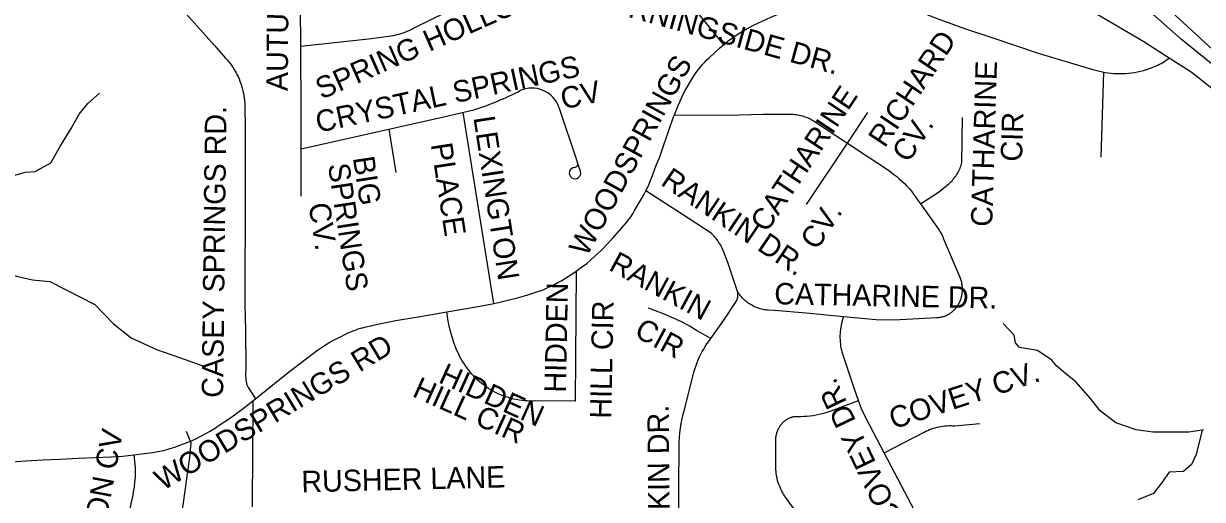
# Model space of a CAD drawing. Extents: x 1670563 to 1761545, y 515755 to 578944.
# Drawn here: x 1683746 to 1687869, y 541194 to 542857 of the extents above; entities that cross this region are included whole.
import ezdxf

# ---------------------------------------------------------------- set-up
doc = ezdxf.new("R2010")
doc.units = 0
for name, color, linetype in [('SHP_LINE', 7, 'Continuous'), ('STREETCL', 7, 'Continuous'), ('STRNAMES', 7, 'Continuous')]:
    doc.layers.add(name, color=color, linetype=linetype)

msp = doc.modelspace()

# ---------------------------------------------------------------- linework, layer by layer
at = {"layer": 'SHP_LINE'}
for points in [[(1689131, 541565), (1689053, 541640), (1688830, 541857), (1688559, 542103), (1688256, 542404), (1687931, 542692), (1687795, 542802), (1687567, 543005), (1687321, 543225), (1687106, 543454), (1686905, 543627)], [(1683447, 542214), (1683506, 542266), (1683570, 542290), (1683604, 542303), (1683694, 542321), (1683752, 542337), (1683786, 542340), (1683841, 542370), (1683875, 542429), (1683912, 542490), (1683940, 542540), (1683971, 542577), (1684011, 542613)], [(1683447, 542214), (1683500, 542137), (1683533, 542087), (1683589, 542054), (1683650, 542004), (1683721, 541974), (1683777, 541961), (1683838, 541955), (1683995, 541875), (1684060, 541807), (1684122, 541758), (1684211, 541718), (1684291, 541690), (1684383, 541657)], [(1687868, 541436), (1687822, 541429), (1687764, 541429), (1687696, 541429), (1687638, 541437), (1687566, 541462), (1687512, 541504), (1687478, 541546), (1687427, 541605), (1687385, 541639), (1687360, 541660), (1687343, 541680), (1687292, 541714), (1687229, 541725), (1687216, 541741), (1687211, 541768), (1687173, 541809)], [(1684242, 540618), (1684235, 540737), (1684256, 540825), (1684263, 540952), (1684290, 541072), (1684316, 541258), (1684327, 541341), (1684332, 541390), (1684316, 541431)], [(1687868, 541436), (1687848, 541351), (1687831, 541316), (1687803, 541292), (1687753, 541289), (1687729, 541254), (1687698, 541215), (1687643, 541192)], [(1687873, 541437), (1687868, 541436)]]:
    msp.add_lwpolyline(points, dxfattribs=at)
at = {"layer": 'STREETCL'}
for points in [[(1687753, 542736.4), (1687664.4, 542793.2), (1687503.4, 542887.4), (1687425.7, 542938.3), (1687385.2, 542965.1), (1687345.3, 542993.3), (1687264.8, 543057.2), (1687055, 543250.4), (1686936.4, 543367.8)], [(1690560.6, 540332.7), (1690505, 540379.3), (1690380.4, 540490.5), (1690084.8, 540762.6), (1689786.5, 541036.3), (1689482.1, 541315.5), (1689180.7, 541593.3), (1688892.1, 541859.2), (1688597, 542129.2), (1688347.9, 542359.8), (1688065.6, 542618.5), (1687817.6, 542847), (1687553.2, 543088.3), (1687466.2, 543168.5)], [(1684715, 542778), (1684962.4, 542805.1), (1685030, 542814.2), (1685037.4, 542815.3), (1685044.7, 542816.7), (1685052, 542818.3), (1685059.2, 542820.1), (1685066.4, 542822.2), (1685073.5, 542824.4), (1685080.5, 542827), (1685087.5, 542829.7), (1685094.3, 542832.7), (1685101.1, 542835.9), (1685107.7, 542839.3), (1685114.2, 542842.9), (1685224.4, 542897.2), (1685329.3, 542947.2), (1685488.8, 543021.7), (1685516.9, 543035.2), (1685545.4, 543047.9), (1685574.2, 543059.9), (1685683, 543100.1)], [(1686009.7, 542942.3), (1686042.5, 542934.3), (1686046.2, 542933.2), (1686049.8, 542932.1), (1686053.3, 542930.8), (1686056.8, 542929.4), (1686060.3, 542927.8), (1686063.7, 542926.2), (1686067, 542924.4), (1686070.3, 542922.6), (1686073.5, 542920.6), (1686076.6, 542918.5), (1686079.7, 542916.3), (1686082.7, 542914), (1686085.6, 542911.6), (1686088.4, 542909.1), (1686091.2, 542906.5), (1686093.8, 542903.8), (1686109.2, 542887.4), (1686194.1, 542782.2)], [(1686756.7, 542966), (1686868.9, 542904.3), (1686892.6, 542893.8), (1686916.7, 542883.9), (1686941, 542874.8), (1687037.4, 542839.8), (1687132.3, 542807.7), (1687294.9, 542753.6), (1687489.9, 542695.2), (1687499.7, 542692.5), (1687509.6, 542690), (1687519.5, 542687.9), (1687524.4, 542687)], [(1684284.1, 542924.8), (1684413.5, 542780.6), (1684452.5, 542736.4), (1684458.3, 542729.8), (1684463.8, 542723.1), (1684469.1, 542716.2), (1684474.2, 542709.1), (1684479, 542701.9), (1684483.6, 542694.4), (1684487.9, 542686.9), (1684492, 542679.2), (1684495.8, 542671.3), (1684499.3, 542663.4), (1684502.6, 542655.3), (1684505.6, 542647.1), (1684508.4, 542638.9), (1684510.8, 542630.5), (1684513, 542622.1), (1684514.9, 542613.6), (1684516.5, 542605), (1684517.8, 542596.4), (1684518.8, 542587.7), (1684519.5, 542579.1), (1684520, 542570.4), (1684520.1, 542561.6), (1684521.1, 542499.2), (1684520.8, 542375.7), (1684520.5, 542304.8), (1684520.8, 542275.3), (1684521.3, 542246.2), (1684521.2, 542141.3), (1684520.2, 542008.2), (1684520.1, 541875.4), (1684521.6, 541785.9), (1684522.9, 541653.7), (1684522.6, 541630.1), (1684522.6, 541625.1), (1684522.8, 541620.2), (1684523.1, 541615.3), (1684523.6, 541610.3), (1684524.2, 541605.4), (1684525, 541600.5), (1684525.4, 541598.9), (1684525.9, 541597.3), (1684526.5, 541595.7), (1684527.1, 541594.2), (1684527.8, 541592.6), (1684528.5, 541591.1), (1684529.3, 541589.6), (1684530.1, 541588.2), (1684531, 541586.7), (1684531.9, 541585.3), (1684557.1, 541545.7)], [(1684716.2, 542253.1), (1684716.2, 542616.4), (1684715.1, 542704.1), (1684715, 542778), (1684715, 542820.5), (1684713.2, 542920)], [(1686194, 542782.3), (1686204.5, 542791.1), (1686210.4, 542795.9), (1686221.7, 542804.6), (1686233.3, 542812.9), (1686245.1, 542820.8), (1686257.3, 542828.3), (1686269.7, 542835.3), (1686299.4, 542850.9), (1686329.5, 542865.6), (1686360, 542879.4), (1686390.9, 542892.4), (1686413.6, 542901.4), (1686436.6, 542909.7), (1686459.9, 542917.2), (1686483.4, 542923.9), (1686507.1, 542929.9)], [(1686022.6, 542537.8), (1686035.3, 542569.9), (1686040.9, 542583.4), (1686047, 542596.6), (1686053.5, 542609.6), (1686060.5, 542622.4), (1686085.9, 542666), (1686092, 542675.7), (1686098.5, 542685.3), (1686105.2, 542694.6), (1686112.3, 542703.7), (1686119.7, 542712.6), (1686127.4, 542721.2), (1686135.4, 542729.5), (1686143.7, 542737.5), (1686180.3, 542770.5), (1686194, 542782.3)], [(1687524.4, 542687), (1687529.5, 542686.1), (1687539.6, 542684.6), (1687549.7, 542683.4), (1687559.9, 542682.6), (1687570.1, 542682.1), (1687580.2, 542681.9), (1687590.4, 542682.1), (1687600.6, 542682.6), (1687611.2, 542683.4), (1687621.9, 542684.6), (1687632.4, 542686.2), (1687642.9, 542688.2), (1687653.4, 542690.5), (1687663.7, 542693.2), (1687674, 542696.2), (1687684.1, 542699.6), (1687694.1, 542703.3), (1687704, 542707.4), (1687713.8, 542711.8), (1687719.7, 542714.7), (1687725.6, 542717.8), (1687731.3, 542721.2), (1687736.9, 542724.7), (1687742.4, 542728.4), (1687747.8, 542732.3), (1687753, 542736.4)], [(1688800.8, 541821.8), (1688630.2, 541982.7), (1688274.1, 542304.3), (1688152.7, 542415.6), (1687998.9, 542551.8), (1687855.4, 542667.6), (1687829.6, 542687.4), (1687753, 542736.4)], [(1687515.3, 542389.9), (1687524.4, 542687)], [(1685618.4, 542564.8), (1685683.9, 542369.9)], [(1684716.4, 542419.6), (1685220.1, 542532.4), (1685320.6, 542554.8)], [(1685391.1, 541878.7), (1685283.4, 542546.5)], [(1685922.8, 542272.5), (1685929, 542285.5), (1685934.9, 542298.8), (1685940.3, 542312.2), (1685945.4, 542325.8), (1685957.6, 542358.9), (1685970.9, 542391.6), (1685985.4, 542432.9), (1686001.9, 542480), (1686019.6, 542530.3), (1686022.6, 542537.8)], [(1686022.6, 542537.8), (1686207.3, 542537), (1686333.2, 542540.1), (1686427.5, 542540.1), (1686432.9, 542540), (1686438.3, 542539.7), (1686443.6, 542539.2), (1686449, 542538.6), (1686454.3, 542537.8), (1686459.6, 542536.7), (1686464.8, 542535.5), (1686470, 542534.2), (1686475.2, 542532.6), (1686480.2, 542530.9), (1686485.3, 542529), (1686490.2, 542526.9), (1686495.1, 542524.6), (1686499.9, 542522.2), (1686504.6, 542519.6), (1686509.3, 542516.9), (1686628.3, 542439)], [(1686628.3, 542439), (1686699.5, 542545.6)], [(1686883.3, 542226.5), (1686950.1, 542270), (1686978.2, 542293.1), (1686982.2, 542296.5), (1686986.1, 542300.1), (1686989.8, 542303.7), (1686993.5, 542307.5), (1686996.9, 542311.4), (1687000.3, 542315.5), (1687003.5, 542319.6), (1687006.5, 542323.9), (1687009.4, 542328.2), (1687012.2, 542332.7), (1687014.8, 542337.3), (1687017.2, 542341.9), (1687019.5, 542346.6), (1687021.6, 542351.4), (1687023.5, 542356.3), (1687025.3, 542361.2), (1687026.8, 542366.2), (1687028.3, 542371.3), (1687029.8, 542529.1)], [(1685023.1, 542488.3), (1685047.6, 542336.4)], [(1686484.8, 542224.1), (1686628.3, 542439)], [(1686628.3, 542439), (1686697, 542394), (1686770.8, 542344.1), (1686780.8, 542337.1), (1686790.5, 542329.8), (1686799.9, 542322.2), (1686809.2, 542314.4), (1686818.1, 542306.2), (1686826.8, 542297.7), (1686835.2, 542288.9), (1686843.4, 542279.9), (1686851.2, 542270.6), (1686858.7, 542261.1), (1686865.9, 542251.4), (1686872.8, 542241.4), (1686883.3, 542226.5)], [(1685693.7, 542340.6), (1685683.9, 542369.9)], [(1685678.6, 541991.7), (1685697.3, 542005.1), (1685715.7, 542018.9), (1685768.4, 542066.6), (1685806.2, 542105.6), (1685846.7, 542152.5), (1685854.7, 542162.1), (1685862.4, 542171.9), (1685869.7, 542182), (1685876.7, 542192.4), (1685883.3, 542203), (1685907.7, 542244.3), (1685915.5, 542258.3), (1685922.8, 542272.5)], [(1686242.8, 541920.6), (1686209.7, 542021.6), (1686194.2, 542061), (1686192, 542066.3), (1686189.6, 542071.6), (1686187, 542076.8), (1686184.3, 542081.9), (1686181.4, 542086.9), (1686178.3, 542091.8), (1686175, 542096.6), (1686171.6, 542101.3), (1686168, 542105.9), (1686164.3, 542110.3), (1686160.4, 542114.6), (1686156.3, 542118.7), (1686152.2, 542122.8), (1686147.9, 542126.6), (1686050.5, 542190), (1685922.8, 542272.5)], [(1686883.3, 542226.5), (1686946.2, 542137.9), (1686948.7, 542134.3), (1686951, 542130.6), (1686953.2, 542126.9), (1686955.3, 542123.1), (1686957.3, 542119.2), (1686959.2, 542115.3), (1686960.9, 542111.3), (1686962.5, 542107.3), (1687020.4, 541970.5), (1687021.9, 541967), (1687023.1, 541963.5), (1687024.3, 541959.9), (1687025.4, 541956.3), (1687026.3, 541952.6), (1687027, 541948.9), (1687027.7, 541945.2), (1687028.2, 541941.5), (1687028.6, 541937.7), (1687028.9, 541934), (1687029, 541930.2), (1687029, 541926.4), (1687028.9, 541922.6), (1687028.6, 541918.9), (1687028.3, 541915.1), (1687027.7, 541911.4), (1687027.1, 541907.7), (1687026.3, 541904), (1687025.4, 541900.3), (1687024.4, 541896.7), (1687023.2, 541893.1), (1687021.9, 541889.6), (1687020.5, 541886.1), (1687019, 541882.6), (1687017.4, 541879.2), (1687015.6, 541875.9), (1687013.7, 541872.6), (1687011.7, 541869.4), (1687009.6, 541866.3), (1687007.9, 541863.8), (1687006, 541861.4), (1687004.1, 541859.1), (1687002.1, 541856.9), (1687000, 541854.7), (1686997.9, 541852.6), (1686995.6, 541850.5), (1686993.4, 541848.6), (1686991, 541846.7), (1686988.6, 541844.9), (1686986.1, 541843.2), (1686983.6, 541841.6), (1686981, 541840), (1686978.3, 541838.6), (1686975.7, 541837.2), (1686972.9, 541835.9), (1686970.2, 541834.8), (1686967.3, 541833.7), (1686964.5, 541832.7), (1686961.6, 541831.8), (1686958.7, 541831), (1686955.8, 541830.3), (1686952.8, 541829.8), (1686949.8, 541829.3), (1686946.9, 541828.9), (1686943.9, 541828.6), (1686940.9, 541828.4), (1686790.9, 541820.7), (1686728, 541821.3), (1686613.7, 541832.1)], [(1685226.2, 541848.9), (1685273.7, 541857.3), (1685328.6, 541867), (1685384.4, 541877.3), (1685407.4, 541882), (1685430.2, 541887.4), (1685477.8, 541900.1), (1685509.4, 541909.3), (1685540.9, 541919.2), (1685553.1, 541923.4), (1685565.3, 541928), (1685577.3, 541933), (1685589.1, 541938.4), (1685600.8, 541944.1), (1685614.7, 541951.5), (1685628.4, 541959.3), (1685641.9, 541967.4), (1685660.4, 541979.3), (1685678.6, 541991.7)], [(1685678.6, 541991.7), (1685675.6, 541537.6)], [(1686150.1, 541756.4), (1686195.2, 541820.5), (1686238.3, 541886), (1686239.1, 541887.2), (1686239.8, 541888.4), (1686240.5, 541889.7), (1686241.1, 541891), (1686241.7, 541892.3), (1686242.2, 541893.7), (1686242.7, 541895), (1686243.1, 541896.4), (1686243.5, 541897.8), (1686243.8, 541899.1), (1686244.1, 541900.5), (1686244.4, 541902), (1686244.6, 541903.4), (1686244.7, 541904.8), (1686244.8, 541906.2), (1686244.8, 541907.7), (1686244.8, 541909.1), (1686244.8, 541910.5), (1686244.7, 541912), (1686244.5, 541913.4), (1686244.3, 541914.8), (1686244.1, 541916.2), (1686243.8, 541917.6), (1686242.8, 541920.6)], [(1686613.7, 541832.1), (1686483.1, 541844.5), (1686372.8, 541853.8), (1686350.4, 541855.3), (1686345.8, 541855.7), (1686341.1, 541856.3), (1686336.5, 541857), (1686331.9, 541857.9), (1686327.4, 541858.9), (1686322.9, 541860.1), (1686318.4, 541861.4), (1686314, 541862.9), (1686309.6, 541864.5), (1686305.3, 541866.3), (1686301, 541868.3), (1686296.8, 541870.3), (1686292.7, 541872.5), (1686288.7, 541874.9), (1686284.7, 541877.4), (1686280.9, 541880), (1686277.1, 541882.8), (1686273.4, 541885.7), (1686269.8, 541888.7), (1686266.4, 541891.8), (1686263, 541895), (1686259.7, 541898.4), (1686256.6, 541901.8), (1686253.6, 541905.4), (1686250.7, 541909.1), (1686247.9, 541912.8), (1686245.3, 541916.7), (1686242.8, 541920.6)], [(1686150.1, 541756.4), (1686099.9, 541784.6), (1686077, 541798.1), (1686053.7, 541810.8), (1686029.9, 541822.7), (1686005.8, 541833.7), (1685981.3, 541843.9), (1685956.4, 541853.2), (1685931.2, 541861.7)], [(1684557.1, 541545.7), (1684570.3, 541556.1), (1684671.7, 541637), (1684734.9, 541686.4), (1684759.8, 541705.2), (1684773.7, 541715.3), (1684787.9, 541725), (1684802.4, 541734.2), (1684817.2, 541742.9), (1684832.3, 541751.1), (1684847.6, 541758.8), (1684879, 541774.5), (1684886.3, 541778), (1684893.6, 541781.2), (1684901.1, 541784.3), (1684908.6, 541787.1), (1684916.3, 541789.6), (1684924, 541792), (1684931.8, 541794), (1684944.5, 541797.2), (1684996, 541809), (1685047.9, 541819), (1685133.4, 541833.7), (1685186.7, 541842), (1685226.2, 541848.9)], [(1685675.6, 541537.6), (1685536.4, 541538.2), (1685526.8, 541537.8), (1685517.2, 541537.8), (1685507.6, 541538), (1685498, 541538.7), (1685488.4, 541539.7), (1685478.9, 541541), (1685469.5, 541542.6), (1685460, 541544.6), (1685450.7, 541546.9), (1685441.5, 541549.5), (1685432.3, 541552.4), (1685423.3, 541555.7), (1685414.3, 541559.3), (1685405.5, 541563.1), (1685396.9, 541567.3), (1685388.4, 541571.8), (1685380, 541576.6), (1685371.9, 541581.7), (1685363.9, 541587), (1685356.1, 541592.7), (1685348.5, 541598.6), (1685341.1, 541604.8), (1685334, 541611.2), (1685327.1, 541617.8), (1685320.4, 541624.7), (1685313.9, 541631.9), (1685307.7, 541639.2), (1685301.8, 541646.8), (1685296.2, 541654.6), (1685290.6, 541662.3), (1685285.3, 541670.2), (1685280.2, 541678.2), (1685275.4, 541686.4), (1685270.9, 541694.8), (1685266.7, 541703.3), (1685262.7, 541711.9), (1685259, 541720.7), (1685255.6, 541729.5), (1685252.5, 541738.5), (1685247.3, 541753.9), (1685242.6, 541769.4), (1685238.3, 541785.1), (1685234.5, 541800.9), (1685231.3, 541816.8), (1685228.5, 541832.8), (1685226.2, 541848.9)], [(1686666.6, 541539.1), (1686651.5, 541582.7), (1686613.7, 541694.6), (1686611.5, 541701.5), (1686609.5, 541708.6), (1686607.8, 541715.6), (1686606.3, 541722.8), (1686605.1, 541730), (1686604.1, 541737.2), (1686603.3, 541744.5), (1686602.9, 541751.7), (1686602.6, 541759), (1686602.6, 541766.3), (1686602.9, 541773.6), (1686603.4, 541780.9), (1686604.2, 541788.1), (1686605.3, 541795.3), (1686606.5, 541802.5), (1686608.1, 541809.7), (1686613.7, 541832.1)], [(1686037.1, 541056.5), (1686037.9, 541241.1), (1686038.7, 541376.9), (1686039.1, 541393.5), (1686040.1, 541410.2), (1686041.6, 541426.7), (1686043.8, 541443.2), (1686046.5, 541459.7), (1686049.7, 541476), (1686053.6, 541492.2), (1686058, 541508.2), (1686089, 541632.2), (1686091.7, 541642.4), (1686094.7, 541652.5), (1686098.1, 541662.4), (1686101.8, 541672.3), (1686105.8, 541682), (1686110.1, 541691.6), (1686114.7, 541701.1), (1686119.7, 541710.3), (1686124.9, 541719.5), (1686130.4, 541728.4), (1686136.2, 541737.2), (1686142.3, 541745.8), (1686150.1, 541756.4)], [(1684131.3, 541349.3), (1684167.9, 541353.9), (1684197.9, 541358.4), (1684227.6, 541363.7), (1684235.6, 541365.3), (1684243.5, 541367.2), (1684251.3, 541369.3), (1684259, 541371.6), (1684266.7, 541374.1), (1684274.3, 541376.9), (1684296, 541384.6), (1684314.4, 541391.5), (1684332.6, 541399), (1684350.5, 541407.2), (1684365.9, 541414.8), (1684381.1, 541422.9), (1684396, 541431.6), (1684416.7, 541444.3), (1684436.9, 541457.5), (1684469, 541479), (1684520, 541516.4), (1684547.3, 541537.9)], [(1684547.3, 541537.9), (1684545, 541174.7), (1684544.9, 541167.6)], [(1684547.3, 541537.9), (1684557.1, 541545.7)], [(1686460.3, 541134.2), (1686411.2, 541202), (1686407.7, 541206.9), (1686404.5, 541211.9), (1686401.4, 541217.1), (1686398.4, 541222.3), (1686395.7, 541227.7), (1686393.1, 541233.1), (1686390.7, 541238.6), (1686388.5, 541244.2), (1686386.5, 541249.9), (1686384.7, 541255.6), (1686383.1, 541261.4), (1686381.6, 541267.2), (1686380.4, 541273.1), (1686379.4, 541279), (1686378.5, 541285), (1686377.9, 541291), (1686377.5, 541296.9), (1686377.2, 541303), (1686377.2, 541309), (1686377.4, 541315), (1686376.9, 541399.8), (1686377, 541402.8), (1686377.1, 541405.9), (1686377.4, 541409), (1686377.7, 541412), (1686378.2, 541415.1), (1686378.7, 541418.1), (1686379.4, 541421.1), (1686380.2, 541424.1), (1686381, 541427), (1686382, 541430), (1686383.1, 541432.8), (1686384.3, 541435.7), (1686385.5, 541438.5), (1686386.9, 541441.3), (1686388.4, 541444), (1686389.9, 541446.6), (1686391.5, 541449.2), (1686393.3, 541451.8), (1686395.1, 541454.3), (1686397, 541456.7), (1686399, 541459), (1686401, 541461.3), (1686403.2, 541463.5), (1686405.4, 541465.7), (1686407.7, 541467.7), (1686409.4, 541469.2), (1686411.2, 541470.6), (1686413, 541471.9), (1686414.9, 541473.2), (1686416.8, 541474.4), (1686418.7, 541475.5), (1686420.7, 541476.6), (1686422.7, 541477.6), (1686424.7, 541478.5), (1686426.8, 541479.4), (1686428.9, 541480.2), (1686431, 541480.9), (1686433.2, 541481.6), (1686435.3, 541482.2), (1686437.5, 541482.7), (1686439.7, 541483.1), (1686442, 541483.5), (1686444.2, 541483.8), (1686446.4, 541484), (1686448.7, 541484.1), (1686450.9, 541484.2), (1686453.2, 541484.2), (1686464.1, 541484.1), (1686474.9, 541484.5), (1686485.8, 541485.2), (1686496.7, 541486.2), (1686507.5, 541487.6), (1686518.2, 541489.4), (1686528.9, 541491.6), (1686539.5, 541494.1), (1686550, 541497), (1686560.4, 541500.2), (1686570.7, 541503.8), (1686666.6, 541539.1)], [(1686755.6, 541356.9), (1686692.6, 541476.5), (1686676.5, 541510.3), (1686666.6, 541539.1)], [(1686755.6, 541356.9), (1686895.8, 541429.4), (1686902.1, 541432.5), (1686908.4, 541435.3), (1686914.8, 541438), (1686921.3, 541440.4), (1686927.8, 541442.6), (1686934.5, 541444.5), (1686941.2, 541446.3), (1686948, 541447.7), (1686954.8, 541449), (1686961.6, 541450), (1686968.5, 541450.8), (1686975.4, 541451.4), (1686982.3, 541451.7), (1686989.3, 541451.7), (1686996.2, 541451.6), (1687003.1, 541451.2), (1687090.3, 541459.5)], [(1683560.3, 541297.5), (1683588.5, 541305.2), (1683631.7, 541315.5), (1683646.9, 541318.3), (1683721.4, 541326.5), (1683753.7, 541328.9), (1683813.5, 541332.3), (1683871.5, 541335), (1683938.4, 541337.6), (1684052.2, 541342.8), (1684091.8, 541345.5), (1684131.3, 541349.3)], [(1684131.3, 541349.3), (1684135.5, 541304.6), (1684136, 541299.2), (1684136.2, 541293.8), (1684136.3, 541288.4), (1684136.2, 541283), (1684136, 541277.6), (1684135.5, 541272.2), (1684134, 541254.9), (1684132, 541237.1), (1684129.5, 541219.4), (1684126.3, 541201.7), (1684122.5, 541184.2), (1684118.1, 541166.9), (1684053.3, 540876.5)], [(1686915.3, 541054.9), (1686887.9, 541105.8), (1686755.6, 541356.9)]]:
    msp.add_lwpolyline(points, dxfattribs=at)
for centre, radius, start, end in [((1684974.3, 543616.1), 1116.3, 288.0745, 297.1191), ((1685524.1, 542531.3), 100, 19.5776, 114.2008), ((1685524.1, 542531.3), 100, 19.5815, 114.1969), ((1685674.7, 542334.3), 20, 94.099, 18.5828), ((1685672.5, 542366.2), 12, 274.099, 18.3203)]:
    msp.add_arc(centre, radius, start, end, dxfattribs=at)

# ---------------------------------------------------------------- texts
at = {"layer": 'STRNAMES'}
for s, rotation, p in [('AUTUMN    DR.', 89.5584, (1684669.9, 542620.5)), ('SPRING HOLLOW DR.', 23.8752, (1684787.9, 542590.6)), ('MORNINGSIDE DR.', 344.4874, (1685701.8, 542923.9)), ('RICHARD', 56.3023, (1686758.2, 542419.5)), ('CRYSTAL SPRINGS', 12.1776, (1684776.2, 542475)), ('WOODSPRINGS', 61.3601, (1685715.6, 542038.8)), ('CATHARINE ', 88.3217, (1687134.1, 542146.1)), (' CV', 12.1776, (1685606.1, 542550.4)), ('CATHARINE', 56.3023, (1686345.2, 542123.2)), ('CASEY SPRINGS RD.', 89.3372, (1684443.7, 541548.7)), ('LEXINGTON ', 278.7173, (1685319, 542528.5)), ('CV.', 56.3023, (1686840.6, 542366.9)), ('CIR', 88.3217, (1687238.4, 542373.7)), ('PLACE', 278.7173, (1685170, 542434.9)), ('SPRINGS', 278.7173, (1684810.1, 542363.3)), ('BIG ', 278.7173, (1684897.3, 542387.9)), ('RANKIN DR.', 326.0193, (1685970.9, 542295.5)), ('CV.', 278.7173, (1684742.4, 542225.2)), (' CV.', 56.3023, (1686504.8, 542038.4)), ('RANKIN ', 331.5871, (1685789, 541997.5)), ('HIDDEN ', 88.8294, (1685642.6, 541566.7)), ('CATHARINE DR.', 358.8816, (1686371.2, 541876)), ('HILL CIR', 88.8294, (1685801.5, 541475.5)), ('CIR', 331.5871, (1685878, 541765.8)), ('WOODSPRINGS RD', 31.072, (1684233.4, 541222.8)), ('HIDDEN ', 335.7672, (1685193.3, 541604.1)), ('COVEY CV.', 18.2349, (1686788.3, 541438.3)), ('HILL CIR', 335.7081, (1685101.9, 541555.9)), ('COVEY DR.', 115.6567, (1686822.9, 541126.5)), ('RANKIN DR.', 90.4878, (1686007.5, 540945.4)), ('HARRISON CV', 79.376, (1683965.8, 540746.3)), ('RUSHER LANE', 1.404, (1684718.3, 541218.5))]:
    msp.add_text(s, height=75, rotation=rotation, dxfattribs=at).set_placement(p)

doc.saveas('drawing.dxf')
